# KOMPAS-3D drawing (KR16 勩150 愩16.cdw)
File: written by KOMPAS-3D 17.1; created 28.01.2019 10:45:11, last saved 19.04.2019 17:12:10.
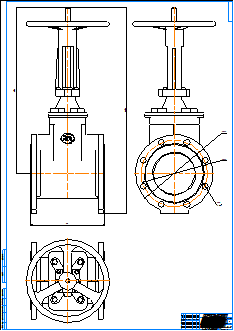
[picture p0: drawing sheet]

Sheet 1: A0, portrait

Title block, sheet 1: name: KR16 Ду150 Ру16; material: Внимание! Данный продукт является объектом авторского права ООО «Торговый Дом АДЛ». / Запрещается изменение, копирование, распространение / (в том числе путем копирования на другие сайты и ресурсы в Интернете) / или любое иное использование информации и объектов без предварительного / согласия правообладателя (ООО «Торговый Дом АДЛ»).; sheets: 1; organisation: ООО "Торговый дом АДЛ"; sheet format: A0; stored path: \\adlc.lan\data\АДЛ_ПКД\3D-модели\ADL production\Клиновые задвижки серии KR ГРАНАР\Клиновые задвижки KR16\Со штурвалом\KOMPAS 2D\KR16 Ду150.cdw

Views: Вид 1, Проекционный вид 2
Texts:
  user
Dimensions and other numbers on the sheet: 267; 597; 739,5; 280; 22; 8 отв.; 240; 1:1; 1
